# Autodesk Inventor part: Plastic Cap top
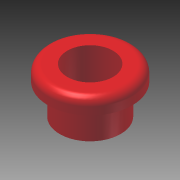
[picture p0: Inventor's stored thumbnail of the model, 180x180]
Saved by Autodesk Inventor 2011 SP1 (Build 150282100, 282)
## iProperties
Created: 2011-10
Part Number: Plastic Cap top
Document SubType Name: Modeling
Designer: sdarley
Density: 1 g/cm^3
Author: sdarley
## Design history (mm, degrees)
sketch "Sketch1"
  geometry: C1 r 4 at (0, 0) reference; C2 r 5.5 at (0, 0) reference; C3 r 3 at (0, 0); 1 further point
  constraints: 1 centre point, 1 coincident
  dimensions: "d0" = 6 diameter of C3
extrude "Extrusion1" new body sketch "Sketch1" distance "d1" = 4; taper "d2" = 0 deg
sketch "Sketch2"
  geometry: C1 r 4 at (0, 0) reference; C2 r 5.5 at (0, 0) reference; C3 r 3 at (0, 0) reference
extrude "Extrusion3" join sketch "Sketch2" distance "d5" = 2; taper "d6" = 0 deg
fillet "Fillet1" dims "d7" = 1
body "Solid1"
node "Reference1"
node "Reference2"
